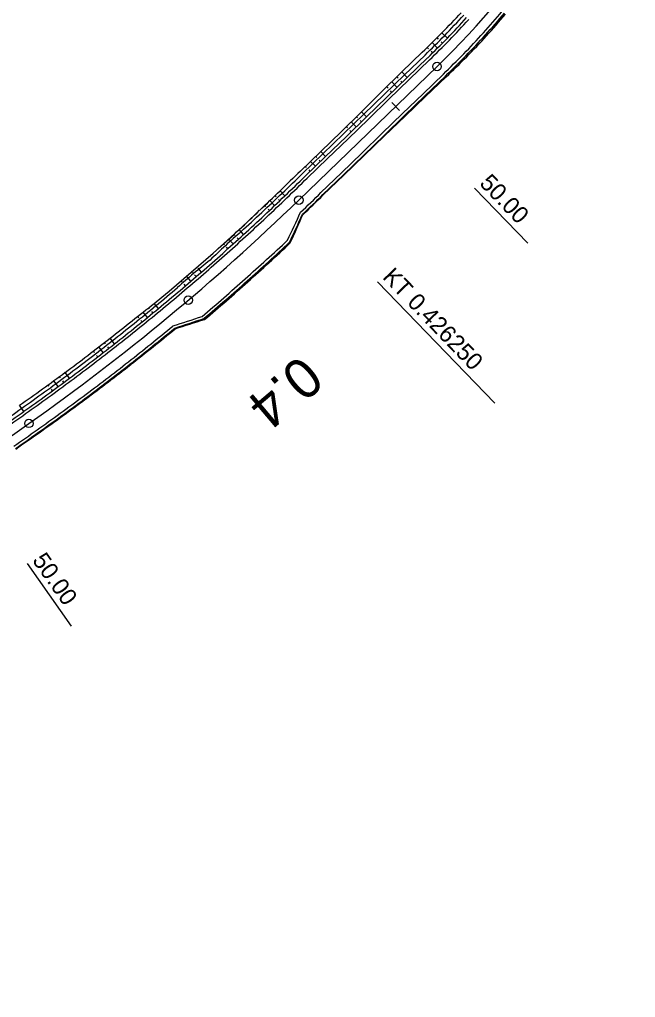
# Model space of a CAD drawing. Extents: x -481645 to -478728, y -1113199 to -1110710.
# Drawn here: x -480321.2 to -480212.6, y -1112822.9 to -1112650.6 of the extents above; entities that cross this region are included whole.
import ezdxf

# ---------------------------------------------------------------- set-up
doc = ezdxf.new("R2010")
doc.units = 0
for name, color, linetype in [('Vrstva 52', 7, 'Continuous'), ('Vrstva 53', 7, 'Continuous'), ('Vrstva 54', 7, 'Continuous'), ('Vrstva 55', 7, 'Continuous'), ('Vrstva 56', 7, 'Continuous'), ('Vrstva 57', 7, 'Continuous'), ('Vrstva 58', 7, 'Continuous'), ('Vrstva 59', 7, 'Continuous'), ('Vrstva 60', 7, 'Continuous'), ('Vrstva 61', 7, 'Continuous'), ('Vrstva 62', 7, 'Continuous')]:
    doc.layers.add(name, color=color, linetype=linetype)

msp = doc.modelspace()

# ---------------------------------------------------------------- linework, layer by layer
at = {"layer": 'Vrstva 52'}
for p, q in [((-480271.95, -1112682.45), (-480247.6, -1112658.91)), ((-480462.96, -1112822.86), (-480319.49, -1112721.76))]:
    msp.add_line(p, q, dxfattribs=at)
for centre, radius, start, end in [((-480351.83, -1112551.04), 150, 314.0166, 338.1186), ((-480549.9, -1112394.79), 400, 305.1722, 314.0166)]:
    msp.add_arc(centre, radius, start, end, dxfattribs=at)
at = {"layer": 'Vrstva 53'}
for p, q in [((-480253.79, -1112659.87), (-480250.2, -1112656.39)), ((-480257.35, -1112663.38), (-480253.79, -1112659.87)), ((-480249.6, -1112664.2), (-480245.98, -1112660.75)), ((-480260.92, -1112666.88), (-480257.35, -1112663.38)), ((-480253.22, -1112667.65), (-480249.6, -1112664.2)), ((-480264.48, -1112670.39), (-480260.92, -1112666.88)), ((-480256.84, -1112671.11), (-480253.22, -1112667.65)), ((-480268.07, -1112673.87), (-480264.48, -1112670.39)), ((-480260.46, -1112674.56), (-480256.84, -1112671.11)), ((-480271.67, -1112677.34), (-480268.07, -1112673.87)), ((-480264.04, -1112678.04), (-480260.46, -1112674.56)), ((-480267.63, -1112681.52), (-480264.04, -1112678.04))]:
    msp.add_line(p, q, dxfattribs=at)
for centre, radius, start, end in [((-480350.22, -1112549.35), 146.44, 314.9702, 316.8803), ((-480351.48, -1112550.64), 152.51, 317.5927, 319.5026), ((-480557.16, -1112342.27), 439.2, 314.3397, 314.9766), ((-480351.2, -1112550.38), 152.49, 315.5394, 317.4493), ((-480565.27, -1112333.2), 457.42, 314.2679, 314.9042), ((-480135.72, -1112821.65), 198.26, 133.2911, 134.7329), ((-480550.75, -1112395.6), 396.54, 313.2913, 314.0075), ((-480515.45, -1112434.89), 343.74, 309.3665, 313.9112), ((-480409.51, -1112538.89), 201.17, 313.4213, 314.8475), ((-480553.45, -1112398.11), 396.57, 313.1073, 313.8236), ((-480640.54, -1112522.73), 403.39, 335.5045, 336.2793), ((-480549.72, -1112394.62), 396.6, 311.653, 312.3692), ((-480550.61, -1112395.44), 404.44, 312.5414, 313.2576), ((-480550.6, -1112395.42), 404.45, 311.8223, 312.5385), ((-480549.89, -1112394.78), 404.45, 310.97, 311.6862), ((-480549.71, -1112394.63), 404.45, 310.2209, 310.9371), ((-480544.32, -1112390.32), 396.55, 307.7915, 308.5078), ((-480548.09, -1112393.36), 396.49, 307.7753, 308.4915), ((-480414.01, -1112320.03), 403.42, 287.347, 288.1204), ((-480549.79, -1112394.7), 402.39, 308.8031, 309.5193), ((-480549.07, -1112394.15), 396.47, 307.2409, 307.9571), ((-480549.81, -1112394.71), 402.39, 308.0906, 308.8068), ((-480549.67, -1112394.62), 396.47, 306.6344, 307.3506), ((-480549.82, -1112394.73), 402.39, 307.3777, 308.0939), ((-480549.59, -1112394.56), 396.46, 305.9036, 306.6198), ((-480546.99, -1112392.72), 396.44, 304.7268, 305.443), ((-480549.8, -1112394.71), 402.39, 306.658, 307.3742), ((-480549.34, -1112394.38), 402.38, 305.8607, 306.5769), ((-480548.93, -1112394.1), 402.37, 305.0737, 305.7899), ((-481012.18, -1111736.08), 1207.1, 304.88445, 305.12192)]:
    msp.add_arc(centre, radius, start, end, dxfattribs=at)
at = {"layer": 'Vrstva 54'}
for p, q in [((-480253.3, -1112660.37), (-480249.71, -1112656.9)), ((-480256.9, -1112663.84), (-480253.3, -1112660.37)), ((-480260.5, -1112667.32), (-480256.9, -1112663.84)), ((-480264.09, -1112670.79), (-480260.5, -1112667.32)), ((-480267.69, -1112674.27), (-480264.09, -1112670.79)), ((-480271.28, -1112677.74), (-480267.69, -1112674.27))]:
    msp.add_line(p, q, dxfattribs=at)
for centre, radius, start, end in [((-480351.83, -1112551.04), 147.08, 315.882, 317.7918), ((-480559.58, -1112342.76), 441.25, 314.6087, 315.2456), ((-480410.97, -1112536.65), 198.54, 313.2742, 314.7145), ((-480549.3, -1112394.22), 397.08, 313.0022, 313.7184), ((-480549.9, -1112394.79), 397.07, 312.4052, 313.1214), ((-480180.38, -1112804.11), 154.39, 131.2251, 133.9765), ((-480201.02, -1112801.72), 138.97, 128.5303, 131.6146), ((-480550.53, -1112395.32), 397.08, 309.6596, 310.3758), ((-480549.9, -1112394.79), 397.08, 308.8242, 309.5404), ((-480549.9, -1112394.79), 397.08, 308.108, 308.8242), ((-480549.9, -1112394.79), 397.08, 307.3918, 308.108), ((-480549.9, -1112394.79), 397.08, 306.6756, 307.3918), ((-480549.9, -1112394.79), 397.08, 305.9594, 306.6756), ((-480549.9, -1112394.79), 397.08, 305.2432, 305.9594), ((-481009.07, -1111746.82), 1191.25, 305.05551, 305.29583)]:
    msp.add_arc(centre, radius, start, end, dxfattribs=at)
at = {"layer": 'Vrstva 55'}
for p, q in [((-480252.84, -1112660.85), (-480249.25, -1112657.38)), ((-480249.72, -1112664.08), (-480246.12, -1112660.61)), ((-480256.44, -1112664.32), (-480252.84, -1112660.85)), ((-480253.31, -1112667.56), (-480249.72, -1112664.08)), ((-480260.03, -1112667.8), (-480256.44, -1112664.32)), ((-480256.91, -1112671.03), (-480253.31, -1112667.56)), ((-480263.63, -1112671.27), (-480260.03, -1112667.8)), ((-480267.23, -1112674.75), (-480263.63, -1112671.27)), ((-480260.5, -1112674.51), (-480256.91, -1112671.03)), ((-480270.82, -1112678.22), (-480267.23, -1112674.75)), ((-480264.1, -1112677.98), (-480260.5, -1112674.51)), ((-480267.69, -1112681.46), (-480264.1, -1112677.98))]:
    msp.add_line(p, q, dxfattribs=at)
for centre, radius, start, end in [((-480351.83, -1112551.04), 147.75, 315.882, 317.7918), ((-480351.83, -1112551.04), 152.25, 317.7918, 319.7017), ((-480351.83, -1112551.04), 152.25, 315.882, 317.7918), ((-480560.52, -1112341.82), 443.25, 314.6088, 315.2456), ((-480566.88, -1112335.45), 456.75, 314.6097, 315.2461), ((-480410.74, -1112536.89), 198.88, 313.275, 314.7136), ((-480549.9, -1112394.79), 397.75, 313.1214, 313.8376), ((-480409.18, -1112538.52), 201.12, 313.2809, 314.7073), ((-480549.9, -1112394.79), 397.75, 312.4052, 313.1214), ((-480638.26, -1112517.75), 403.25, 334.736, 335.5065), ((-480549.9, -1112394.79), 397.75, 311.689, 312.4052), ((-480549.9, -1112394.79), 404.25, 312.4052, 313.1214), ((-480549.9, -1112394.79), 397.75, 310.9728, 311.689), ((-480549.9, -1112394.79), 404.25, 311.689, 312.4052), ((-480549.9, -1112394.79), 397.75, 310.2566, 310.9728), ((-480549.9, -1112394.79), 404.25, 310.9728, 311.689), ((-480549.9, -1112394.79), 397.75, 309.5404, 310.2566), ((-480549.9, -1112394.79), 404.25, 310.2566, 310.9728), ((-480549.9, -1112394.79), 397.75, 308.8242, 309.5404), ((-480417.57, -1112321.2), 403.25, 287.8715, 288.6421), ((-480549.9, -1112394.79), 397.75, 308.108, 308.8242), ((-480549.9, -1112394.79), 402.25, 308.8242, 309.5404), ((-480549.9, -1112394.79), 397.75, 307.3918, 308.108), ((-480549.9, -1112394.79), 402.25, 308.108, 308.8242), ((-480549.9, -1112394.79), 397.75, 306.6756, 307.3918), ((-480549.9, -1112394.79), 402.25, 307.3918, 308.108), ((-480549.9, -1112394.79), 397.75, 305.9594, 306.6756), ((-480549.9, -1112394.79), 402.25, 306.6756, 307.3918), ((-480549.9, -1112394.79), 397.75, 305.2432, 305.9594), ((-480549.9, -1112394.79), 402.25, 305.9594, 306.6756), ((-481009.83, -1111745.73), 1193.25, 305.0557, 305.29565), ((-480549.9, -1112394.79), 402.25, 305.2432, 305.9594), ((-481015.02, -1111738.37), 1206.75, 305.05694, 305.29448)]:
    msp.add_arc(centre, radius, start, end, dxfattribs=at)
at = {"layer": 'Vrstva 56'}
for p, q in [((-480252.49, -1112661.21), (-480248.9, -1112657.73)), ((-480250.06, -1112663.73), (-480246.47, -1112660.25)), ((-480256.09, -1112664.68), (-480252.49, -1112661.21)), ((-480253.66, -1112667.2), (-480250.06, -1112663.73)), ((-480259.69, -1112668.16), (-480256.09, -1112664.68)), ((-480257.25, -1112670.67), (-480253.66, -1112667.2)), ((-480263.28, -1112671.63), (-480259.69, -1112668.16)), ((-480260.85, -1112674.15), (-480257.25, -1112670.67)), ((-480266.88, -1112675.11), (-480263.28, -1112671.63)), ((-480264.45, -1112677.62), (-480260.85, -1112674.15)), ((-480270.47, -1112678.58), (-480266.88, -1112675.11)), ((-480268.04, -1112681.1), (-480264.45, -1112677.62))]:
    msp.add_line(p, q, dxfattribs=at)
for centre, radius, start, end in [((-480351.83, -1112551.04), 151.75, 317.7918, 319.7017), ((-480351.83, -1112551.04), 148.25, 315.882, 317.7918), ((-480351.83, -1112551.04), 151.75, 315.882, 317.7918), ((-480561.23, -1112341.11), 444.75, 314.6089, 315.2457), ((-480566.18, -1112336.15), 455.25, 314.6096, 315.246), ((-480410.57, -1112537.07), 199.12, 313.2757, 314.7129), ((-480409.36, -1112538.34), 200.88, 313.2803, 314.708), ((-480549.9, -1112394.79), 398.25, 313.1214, 313.8376), ((-480638.22, -1112517.75), 402.75, 334.7603, 335.531), ((-480549.9, -1112394.79), 398.25, 312.4052, 313.1214), ((-480549.9, -1112394.79), 398.25, 311.689, 312.4052), ((-480549.9, -1112394.79), 403.75, 312.4052, 313.1214), ((-480549.9, -1112394.79), 398.25, 310.9728, 311.689), ((-480549.9, -1112394.79), 403.75, 311.689, 312.4052), ((-480549.9, -1112394.79), 398.25, 310.2566, 310.9728), ((-480549.9, -1112394.79), 403.75, 310.9728, 311.689), ((-480549.9, -1112394.79), 398.25, 309.5404, 310.2566), ((-480549.9, -1112394.79), 403.75, 310.2566, 310.9728), ((-480549.9, -1112394.79), 398.25, 308.8242, 309.5404), ((-480417.57, -1112321.24), 402.75, 287.8471, 288.6177), ((-480549.9, -1112394.79), 398.25, 308.108, 308.8242), ((-480549.9, -1112394.79), 401.75, 308.8242, 309.5404), ((-480549.9, -1112394.79), 398.25, 307.3918, 308.108), ((-480549.9, -1112394.79), 401.75, 308.108, 308.8242), ((-480549.9, -1112394.79), 398.25, 306.6756, 307.3918), ((-480549.9, -1112394.79), 401.75, 307.3918, 308.108), ((-480549.9, -1112394.79), 401.75, 306.6756, 307.3918), ((-480549.9, -1112394.79), 398.25, 305.9594, 306.6756), ((-480549.9, -1112394.79), 398.25, 305.2432, 305.9594), ((-480549.9, -1112394.79), 401.75, 305.9594, 306.6756), ((-481010.41, -1111744.91), 1194.75, 305.05584, 305.29552), ((-480549.9, -1112394.79), 401.75, 305.2432, 305.9594), ((-481014.44, -1111739.19), 1205.25, 305.05681, 305.29461)]:
    msp.add_arc(centre, radius, start, end, dxfattribs=at)
at = {"layer": 'Vrstva 57'}
for p, q in [((-480252.49, -1112661.21), (-480248.9, -1112657.73)), ((-480250.06, -1112663.73), (-480246.47, -1112660.25)), ((-480256.09, -1112664.68), (-480252.49, -1112661.21)), ((-480253.66, -1112667.2), (-480250.06, -1112663.73)), ((-480259.69, -1112668.16), (-480256.09, -1112664.68)), ((-480257.25, -1112670.67), (-480253.66, -1112667.2)), ((-480263.28, -1112671.63), (-480259.69, -1112668.16)), ((-480260.85, -1112674.15), (-480257.25, -1112670.67)), ((-480266.88, -1112675.11), (-480263.28, -1112671.63)), ((-480264.45, -1112677.62), (-480260.85, -1112674.15)), ((-480270.47, -1112678.58), (-480266.88, -1112675.11)), ((-480268.04, -1112681.1), (-480264.45, -1112677.62))]:
    msp.add_line(p, q, dxfattribs=at)
for centre, radius, start, end in [((-480351.83, -1112551.04), 151.75, 317.7918, 319.7017), ((-480351.83, -1112551.04), 148.25, 315.882, 317.7918), ((-480351.83, -1112551.04), 151.75, 315.882, 317.7918), ((-480561.23, -1112341.11), 444.75, 314.6089, 315.2457), ((-480566.18, -1112336.15), 455.25, 314.6096, 315.246), ((-480410.57, -1112537.07), 199.12, 313.2757, 314.7129), ((-480409.36, -1112538.34), 200.88, 313.2803, 314.708), ((-480549.9, -1112394.79), 398.25, 313.1214, 313.8376), ((-480638.22, -1112517.75), 402.75, 334.7603, 335.531), ((-480549.9, -1112394.79), 398.25, 312.4052, 313.1214), ((-480549.9, -1112394.79), 398.25, 311.689, 312.4052), ((-480549.9, -1112394.79), 403.75, 312.4052, 313.1214), ((-480549.9, -1112394.79), 398.25, 310.9728, 311.689), ((-480549.9, -1112394.79), 403.75, 311.689, 312.4052), ((-480549.9, -1112394.79), 398.25, 310.2566, 310.9728), ((-480549.9, -1112394.79), 403.75, 310.9728, 311.689), ((-480549.9, -1112394.79), 398.25, 309.5404, 310.2566), ((-480549.9, -1112394.79), 403.75, 310.2566, 310.9728), ((-480549.9, -1112394.79), 398.25, 308.8242, 309.5404), ((-480417.57, -1112321.24), 402.75, 287.8471, 288.6177), ((-480549.9, -1112394.79), 398.25, 308.108, 308.8242), ((-480549.9, -1112394.79), 401.75, 308.8242, 309.5404), ((-480549.9, -1112394.79), 398.25, 307.3918, 308.108), ((-480549.9, -1112394.79), 401.75, 308.108, 308.8242), ((-480549.9, -1112394.79), 398.25, 306.6756, 307.3918), ((-480549.9, -1112394.79), 401.75, 307.3918, 308.108), ((-480549.9, -1112394.79), 401.75, 306.6756, 307.3918), ((-480549.9, -1112394.79), 398.25, 305.9594, 306.6756), ((-480549.9, -1112394.79), 398.25, 305.2432, 305.9594), ((-480549.9, -1112394.79), 401.75, 305.9594, 306.6756), ((-481010.41, -1111744.91), 1194.75, 305.05584, 305.29552), ((-480549.9, -1112394.79), 401.75, 305.2432, 305.9594), ((-481014.44, -1111739.19), 1205.25, 305.05681, 305.29461)]:
    msp.add_arc(centre, radius, start, end, dxfattribs=at)
at = {"layer": 'Vrstva 58'}
for p, q in [((-480254.18, -1112666.66), (-480255.57, -1112665.22)), ((-480240.98, -1112680.32), (-480231.6, -1112690.03)), ((-480319.82, -1112746.46), (-480312.04, -1112757.5))]:
    msp.add_line(p, q, dxfattribs=at)
at = {"layer": 'Vrstva 59'}
msp.add_line((-480258.06, -1112696.83), (-480237.42, -1112718.19), dxfattribs=at)
for centre in [(-480247.6, -1112658.91), (-480271.95, -1112682.44), (-480319.49, -1112721.76)]:
    msp.add_circle(centre, 0.75, dxfattribs=at)
at = {"layer": 'Vrstva 60'}
msp.add_circle((-480291.42, -1112700.05), 0.75, dxfattribs=at)
at = {"layer": 'Vrstva 61'}
for p, q in [((-480245.76, -1112653.9), (-480246.73, -1112652.96)), ((-480247.49, -1112655.65), (-480248.45, -1112654.69)), ((-480247.34, -1112654.07), (-480247.58, -1112653.82)), ((-480246.62, -1112654.78), (-480246.86, -1112654.54)), ((-480249.07, -1112655.79), (-480249.32, -1112655.54)), ((-480248.36, -1112656.52), (-480248.6, -1112656.28)), ((-480252.84, -1112660.85), (-480253.79, -1112659.87)), ((-480254.64, -1112662.59), (-480255.57, -1112661.62)), ((-480254.44, -1112660.99), (-480254.68, -1112660.75)), ((-480253.74, -1112661.72), (-480253.97, -1112661.48)), ((-480256.23, -1112662.74), (-480256.46, -1112662.5)), ((-480255.54, -1112663.46), (-480255.77, -1112663.22)), ((-480260.03, -1112667.8), (-480260.92, -1112666.88)), ((-480261.83, -1112669.53), (-480262.7, -1112668.64)), ((-480261.6, -1112667.97), (-480261.81, -1112667.76)), ((-480260.93, -1112668.67), (-480261.16, -1112668.43)), ((-480263.39, -1112669.72), (-480263.59, -1112669.52)), ((-480262.73, -1112670.4), (-480262.96, -1112670.16)), ((-480267.23, -1112674.75), (-480268.07, -1112673.87)), ((-480269.02, -1112676.48), (-480269.87, -1112675.61)), ((-480268.78, -1112674.94), (-480268.97, -1112674.74)), ((-480268.12, -1112675.61), (-480268.36, -1112675.38)), ((-480270.58, -1112676.67), (-480270.77, -1112676.47)), ((-480269.92, -1112677.35), (-480270.15, -1112677.11)), ((-480274.41, -1112681.69), (-480275.26, -1112680.81)), ((-480276.21, -1112683.41), (-480277.05, -1112682.52)), ((-480275.96, -1112681.87), (-480276.15, -1112681.67)), ((-480275.31, -1112682.55), (-480275.54, -1112682.31)), ((-480277.76, -1112683.57), (-480277.94, -1112683.38)), ((-480277.11, -1112684.26), (-480277.35, -1112684.01)), ((-480281.67, -1112688.49), (-480282.44, -1112687.64)), ((-480283.51, -1112690.16), (-480284.28, -1112689.3)), ((-480283.2, -1112688.65), (-480283.36, -1112688.47)), ((-480282.59, -1112689.32), (-480282.82, -1112689.07)), ((-480285.04, -1112690.31), (-480285.2, -1112690.13)), ((-480284.43, -1112690.99), (-480284.66, -1112690.74)), ((-480289.1, -1112695.1), (-480289.69, -1112694.42)), ((-480292.51, -1112696.84), (-480292.62, -1112696.71)), ((-480290.98, -1112696.72), (-480291.64, -1112695.95)), ((-480290.63, -1112695.23), (-480290.67, -1112695.18)), ((-480290.04, -1112695.91), (-480290.31, -1112695.59)), ((-480291.92, -1112697.53), (-480292.16, -1112697.25)), ((-480298.23, -1112701.6), (-480298.39, -1112701.41)), ((-480296.68, -1112701.52), (-480297.42, -1112700.64)), ((-480300.16, -1112703.15), (-480300.34, -1112702.94)), ((-480299.57, -1112703.89), (-480299.78, -1112703.63)), ((-480298.61, -1112703.1), (-480299.36, -1112702.17)), ((-480297.64, -1112702.31), (-480297.86, -1112702.06)), ((-480304.43, -1112707.76), (-480305.21, -1112706.76)), ((-480306.39, -1112709.29), (-480307.17, -1112708.28)), ((-480306.01, -1112707.76), (-480306.19, -1112707.52)), ((-480305.41, -1112708.52), (-480305.61, -1112708.26)), ((-480307.97, -1112709.27), (-480308.16, -1112709.03)), ((-480307.38, -1112710.05), (-480307.58, -1112709.78)), ((-480313.91, -1112713.75), (-480314.1, -1112713.5)), ((-480312.33, -1112713.8), (-480313.1, -1112712.77)), ((-480315.91, -1112715.22), (-480316.09, -1112714.97)), ((-480315.33, -1112716.01), (-480315.53, -1112715.74)), ((-480314.33, -1112715.27), (-480315.09, -1112714.24)), ((-480313.33, -1112714.54), (-480313.53, -1112714.27)), ((-480320.38, -1112719.64), (-480321.15, -1112718.54))]:
    msp.add_line(p, q, dxfattribs=at)
at = {"layer": 'Vrstva 62'}
for p, q in [((-480237.37, -1112651.43), (-480237.17, -1112651.61)), ((-480236.33, -1112650.65), (-480236.33, -1112650.65)), ((-480238.21, -1112652.38), (-480238.11, -1112652.47)), ((-480238.02, -1112652.55), (-480238.02, -1112652.55)), ((-480242.53, -1112657.03), (-480242.37, -1112657.18)), ((-480244.31, -1112658.83), (-480244.16, -1112658.98)), ((-480243.42, -1112657.94), (-480243.34, -1112658.01)), ((-480243.26, -1112658.09), (-480243.26, -1112658.09)), ((-480245.21, -1112659.73), (-480245.14, -1112659.8)), ((-480245.07, -1112659.87), (-480245.07, -1112659.87)), ((-480249.72, -1112664.08), (-480249.6, -1112664.2)), ((-480251.51, -1112665.82), (-480251.41, -1112665.93)), ((-480250.61, -1112664.95), (-480250.56, -1112665.01)), ((-480250.51, -1112665.06), (-480250.51, -1112665.06)), ((-480252.41, -1112666.69), (-480252.36, -1112666.74)), ((-480252.32, -1112666.79), (-480252.32, -1112666.79)), ((-480257.8, -1112671.9), (-480257.77, -1112671.94)), ((-480257.74, -1112671.97), (-480257.74, -1112671.97)), ((-480256.91, -1112671.03), (-480256.84, -1112671.11)), ((-480259.6, -1112673.64), (-480259.58, -1112673.67)), ((-480259.55, -1112673.7), (-480259.55, -1112673.7)), ((-480258.7, -1112672.77), (-480258.65, -1112672.83)), ((-480265, -1112678.85), (-480264.97, -1112678.88)), ((-480264.94, -1112678.91), (-480264.94, -1112678.91)), ((-480264.1, -1112677.98), (-480264.04, -1112678.04)), ((-480266.79, -1112680.59), (-480266.77, -1112680.62)), ((-480266.74, -1112680.65), (-480266.74, -1112680.65)), ((-480265.9, -1112679.72), (-480265.84, -1112679.78)), ((-480271.86, -1112686.17), (-480271.82, -1112686.21)), ((-480271.78, -1112686.25), (-480271.78, -1112686.25)), ((-480271.3, -1112684.94), (-480271.23, -1112685.01)), ((-480272.43, -1112687.4), (-480272.33, -1112687.5)), ((-480273, -1112688.62), (-480272.94, -1112688.68)), ((-480272.89, -1112688.74), (-480272.89, -1112688.74)), ((-480277.29, -1112693.28), (-480277.16, -1112693.43)), ((-480279.16, -1112694.98), (-480279.03, -1112695.13)), ((-480278.22, -1112694.14), (-480278.16, -1112694.21)), ((-480278.09, -1112694.28), (-480278.09, -1112694.28)), ((-480280.1, -1112695.83), (-480280.03, -1112695.9)), ((-480279.96, -1112695.98), (-480279.96, -1112695.98)), ((-480284.83, -1112700.01), (-480284.7, -1112700.16)), ((-480286.75, -1112701.66), (-480286.61, -1112701.81)), ((-480285.79, -1112700.83), (-480285.72, -1112700.91)), ((-480285.66, -1112700.99), (-480285.66, -1112700.99)), ((-480287.71, -1112702.48), (-480287.64, -1112702.55)), ((-480287.58, -1112702.63), (-480287.58, -1112702.63)), ((-480293.82, -1112705), (-480293.73, -1112705.11)), ((-480295.76, -1112706.59), (-480295.67, -1112706.7)), ((-480294.79, -1112705.79), (-480294.74, -1112705.85)), ((-480294.7, -1112705.91), (-480294.7, -1112705.91)), ((-480296.74, -1112707.38), (-480296.69, -1112707.44)), ((-480296.65, -1112707.49), (-480296.65, -1112707.49)), ((-480302.64, -1112712.07), (-480302.6, -1112712.13)), ((-480302.56, -1112712.19), (-480302.56, -1112712.19)), ((-480301.65, -1112711.3), (-480301.57, -1112711.41)), ((-480304.63, -1112713.61), (-480304.59, -1112713.67)), ((-480304.55, -1112713.73), (-480304.55, -1112713.73)), ((-480303.64, -1112712.84), (-480303.55, -1112712.96)), ((-480309.64, -1112717.41), (-480309.56, -1112717.52)), ((-480311.66, -1112718.9), (-480311.58, -1112719.01)), ((-480310.65, -1112718.16), (-480310.61, -1112718.21)), ((-480310.57, -1112718.27), (-480310.57, -1112718.27)), ((-480312.68, -1112719.64), (-480312.64, -1112719.7)), ((-480312.6, -1112719.75), (-480312.6, -1112719.75)), ((-480318.81, -1112724.03), (-480318.77, -1112724.08)), ((-480318.74, -1112724.12), (-480318.74, -1112724.12)), ((-480317.78, -1112723.31), (-480317.72, -1112723.41)), ((-480320.85, -1112725.47), (-480320.82, -1112725.52)), ((-480320.79, -1112725.56), (-480320.79, -1112725.56)), ((-480319.83, -1112724.75), (-480319.77, -1112724.84))]:
    msp.add_line(p, q, dxfattribs=at)

# ---------------------------------------------------------------- texts
at = {"layer": 'Vrstva 58'}
for height, rotation, p in [(3, 314.0166, (-480240.26, -1112679.63)), (2.999, 305.1722, (-480319.01, -1112745.89))]:
    msp.add_text('50.00', height=height, rotation=rotation, dxfattribs=at).set_placement(p)
at = {"layer": 'Vrstva 59'}
msp.add_text('KT 0.426250', height=3, rotation=314.0166, dxfattribs=at).set_placement((-480257.34, -1112696.13))
at = {"layer": 'Vrstva 60'}
msp.add_text('0.4', height=7, rotation=220.211, dxfattribs=at).set_placement((-480271.59, -1112709.48))

doc.saveas('drawing.dxf')
